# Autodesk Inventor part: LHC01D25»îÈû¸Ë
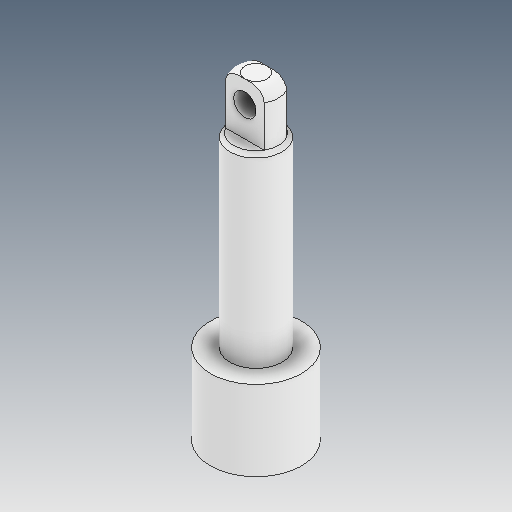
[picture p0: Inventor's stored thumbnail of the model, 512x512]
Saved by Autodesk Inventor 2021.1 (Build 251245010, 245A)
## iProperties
Created: 2021-06
Part Number: LHC01D25»îÈû¸Ë
Material: Ogólny
Document SubType Name: Modeling
Designer: user
Density: 1 g/cm^3
Appearance: Domyślna
Author: user
Revision Number: ÈÎºÎ
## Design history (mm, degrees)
feature "ÊäÈë1"
node "Bryła1"
